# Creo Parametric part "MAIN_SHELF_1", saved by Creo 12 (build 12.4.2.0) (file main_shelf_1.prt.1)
Units: Custom; MM, KILOGRAM, SECS

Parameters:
  PTC_WM_ITERATION = "0"
  PTC_WM_VERSION = "-.0"
  PTC_WM_LIFECYCLE_STATE = "In Work"
  PTC_WM_LIFECYCLE = "MO_CADDocument"
  PTC_WM_CREATED_BY = "Maximilian Roepper (Z0017RMS: MO)"
  PTC_WM_CREATED_ON = "18-Sep-26 11:36:42 AM"
  PTC_WM_MODIFIED_BY = "Maximilian Roepper (Z0017RMS: MO)"
  PTC_WM_MODIFIED_ON = "18-Sep-26 11:36:46 AM"
  PDMLINKNUMBER = "PDM000071455297"
  PTC_WM_NAME = "main_shelf_1.prt"
  PTC_WM_NUMBER = "PDM000071455297"

Other parameters: WEIGHT, WEIGHT_FACTOR, WEIGHT_ADD, _MASS_TEMP, _DIFF_TEMP, MC_ERRORS, SUPPLIER

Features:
  1. coordinate system
  2. datum plane "PRT_YZ"
  3. datum plane "PRT_XY"
  4. datum plane "PRT_XZ"
  5. coordinate system
  6. datum axis
  7. datum axis
  8. datum axis
  9. coordinate system
  10. imported feature

Other named items: PRT, SIEMENS_MO, DRW_VIEW_ORG, PRT_X, PRT_Y, PRT_Z, CS0, ROUGH_GROB

Layers: 00_STD_CSYS-KSYS, 01_STD_PLANES-EBENEN, 02_STD_AXES-ACHSEN, 03_STD_CSYS-KSYS, 24_IMPORT_FEAT-IMPORT_KE

Surfaces: 159 plane, 14 cylinder, 2 ruled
